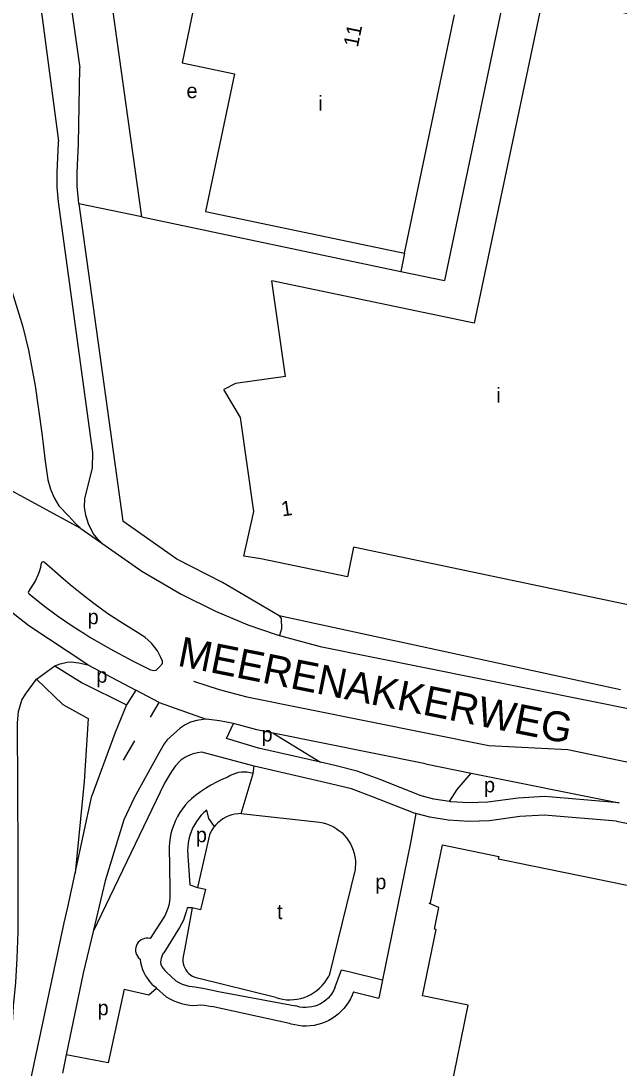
# Model space of a CAD drawing. Extents: x 157699 to 159683, y 381451 to 383293.
# Drawn here: x 157866.4 to 158027.2, y 382131.3 to 382412.9 of the extents above; entities that cross this region are included whole.
import ezdxf

# ---------------------------------------------------------------- set-up
doc = ezdxf.new("R2010")
doc.units = 0
for name, color, linetype in [('BLT_Basislijn', 7, 'Continuous'), ('BLT_Bebouwing', 7, 'Continuous'), ('BLT_Centroide', 7, 'Continuous'), ('BLT_Huisnummer', 7, 'Continuous'), ('BLT_Straatnaam_hoofdweg', 7, 'Continuous'), ('BLT_Vlakafsluiter', 7, 'Continuous')]:
    doc.layers.add(name, color=color, linetype=linetype)

msp = doc.modelspace()

# ---------------------------------------------------------------- linework, layer by layer
at = {"layer": 'BLT_Basislijn'}
for p, q in [((157872.09, 382472.97), (157882.28, 382400.27)), ((157866.68, 382454.83), (157876.58, 382380.56)), ((158001.58, 382444.81), (157980.31, 382343.07)), ((157898.92, 382360.23), (157882.04, 382363.73)), ((157882.04, 382363.73), (157893.81, 382278.36)), ((157898.92, 382360.23), (157968.55, 382345.54)), ((157969.59, 382350.49), (157968.55, 382345.54)), ((157968.55, 382345.54), (157980.31, 382343.07)), ((157884.42, 382239.74), (157897.33, 382232.92)), ((157870.66, 382235.92), (157875.53, 382239.49)), ((157901.27, 382225.73), (157903.61, 382229.63)), ((157934.26, 382221.36), (157946.93, 382213.56)), ((157893.97, 382214.09), (157897.06, 382219.34)), ((157929.17, 382212.52), (157915.11, 382216.32)), ((157928.85, 382210.55), (157929.17, 382212.52)), ((157925.66, 382199.77), (157946.74, 382197.44)), ((157972.62, 382199.75), (157972.44, 382198.77)), ((158026.58, 382197.69), (158050, 382192.97)), ((157917.11, 382194.04), (157913.9, 382179.85)), ((157906.37, 382187.82), (157906.46, 382177.08)), ((157956.26, 382184.71), (157949.27, 382156.23)), ((157912.45, 382174.4), (157910.51, 382163.61)), ((157912.45, 382174.4), (157911.14, 382174.45)), ((157904.77, 382171.72), (157901.15, 382166.19)), ((157909.05, 382169.12), (157904.87, 382162.35)), ((157910.51, 382163.61), (157910.05, 382161.33)), ((157905.54, 382157.15), (157908.12, 382154.77)), ((157934.99, 382150.3), (157913.9, 382155.55)), ((157954.62, 382157.33), (157963.66, 382155.07)), ((157894.23, 382152.57), (157889.92, 382132.71)), ((157902.9, 382152.8), (157902.26, 382153.36)), ((157905.51, 382150.5), (157902.9, 382152.8)), ((157963.66, 382155.07), (157962.66, 382150.17)), ((157919.53, 382151.89), (157940.23, 382148.05)), ((157955.81, 382151.88), (157962.66, 382150.17)), ((157938.66, 382143.3), (157917.74, 382147.86)), ((157878.62, 382134.87), (157877.6, 382129.97)), ((157889.92, 382132.71), (157878.62, 382134.87))]:
    msp.add_line(p, q, dxfattribs=at)
for points in [[(157898.92, 382360.23), (157888.73, 382433.33), (157887.31, 382443.49)], [(157842.49, 382416.11), (157844.46, 382406.06), (157846.72, 382396.15), (157849.16, 382386.42), (157851.39, 382378.58), (157854.48, 382368.73), (157861.08, 382349.18), (157864.09, 382339.92), (157866.95, 382330.66), (157868.51, 382324.33), (157870.3, 382314.78), (157872.07, 382302.05), (157872.93, 382294.52), (157873.7, 382289.49), (157874.36, 382286.95), (157875.34, 382284.62), (157876.6, 382282.47), (157879.28, 382279.71), (157880.94, 382277.93), (157882.56, 382276.42)], [(157882.04, 382363.73), (157881.89, 382364.83), (157881.58, 382368.49), (157881.55, 382372.14), (157881.93, 382379.89), (157882.28, 382400.27)], [(157888.17, 382272.5), (157887.12, 382273.51), (157885.9, 382275.07), (157884.61, 382277.7), (157883.9, 382280.03), (157883.5, 382282.17), (157883.65, 382284.48), (157885.71, 382292.61), (157885.81, 382296.89), (157876.56, 382364.24), (157876.22, 382368.24), (157876.19, 382372.25), (157876.58, 382380.06), (157876.58, 382380.56)], [(157882.56, 382276.42), (157888.17, 382272.5)], [(157920.63, 382261.91), (157908.34, 382268.17), (157893.81, 382278.36)], [(157888.17, 382272.5), (157898.92, 382264.98), (157909.49, 382258.73), (157918.7, 382254.18), (157927.48, 382250.55), (157935.02, 382247.89), (157935.97, 382247.63)], [(157872.79, 382267.31), (157872.47, 382267.48), (157872.09, 382267.35), (157871.79, 382266.77), (157871.68, 382265.89), (157871.38, 382264.79), (157870.99, 382263.85), (157870.4, 382262.43), (157869.77, 382261.47), (157868.46, 382259.48), (157868.42, 382259.28), (157868.5, 382259.05)], [(157868.5, 382259.05), (157868.65, 382258.88), (157872.4, 382255.83), (157876.26, 382252.98), (157880.21, 382250.28), (157883.6, 382248.07), (157884.95, 382247.23), (157890.44, 382244.03), (157896.43, 382240.83), (157901.28, 382238.43), (157902.2, 382238.23), (157902.77, 382238.34), (157903.15, 382238.64), (157903.71, 382239.23), (157904.46, 382240.09), (157904.54, 382240.44), (157904.47, 382240.79), (157904.07, 382241.76), (157903.11, 382243.55), (157901.58, 382245.56), (157899.71, 382247.2), (157897.31, 382248.75), (157893.98, 382250.78), (157889.81, 382253.49), (157886.04, 382256.24), (157883.24, 382258.36), (157879.66, 382261.29), (157877.77, 382262.89), (157874.88, 382265.45), (157872.79, 382267.31)], [(157935.82, 382252.96), (157920.63, 382261.91)], [(158027.64, 382233.05), (157935.82, 382252.96)], [(157935.82, 382252.96), (157936.38, 382252.21), (157936.45, 382249.43), (157935.97, 382247.63)], [(157935.97, 382247.63), (157946.89, 382244.69), (158075.13, 382218.86), (158097.02, 382209.33), (158189.06, 382190.81)], [(157875.53, 382239.49), (157876.97, 382240.03), (157878.88, 382240.5), (157879.93, 382240.61), (157881.97, 382240.29), (157884.42, 382239.74)], [(157875.53, 382239.49), (157882.94, 382234.92), (157894.8, 382229.01)], [(157870.06, 381934.31), (157867.05, 381973.8), (157865.68, 381993.87), (157864.55, 382022.12), (157863.4, 382041.04), (157863.08, 382054.8), (157862.87, 382062.83), (157862.77, 382082.25), (157862.74, 382092.84), (157862.8, 382114.69), (157863.2, 382126.22), (157863.95, 382140.63), (157864.47, 382147.95), (157865.05, 382154.36), (157865.43, 382160.91), (157865.68, 382167.86), (157865.71, 382188.66), (157865.51, 382224.16), (157865.78, 382227.21), (157866.65, 382230.22), (157867.7, 382231.89), (157870.66, 382235.92)], [(157870.66, 382235.92), (157877.71, 382229.09), (157884.48, 382225.3), (157883.43, 382208.35), (157881, 382183.71)], [(157912.82, 382235.37), (157919.74, 382233.13), (157927.13, 382231.2), (157992.2, 382218.03), (158013.48, 382217.01), (158148.74, 382188.63), (158163.94, 382185.79)], [(157897.33, 382232.92), (157894.8, 382229.01)], [(157894.8, 382229.01), (157891.8, 382221.56), (157885.54, 382204.57)], [(157916.22, 382225.12), (157915.45, 382225.03), (157913.73, 382224.81), (157912.06, 382224.32), (157910.59, 382223.63), (157909.22, 382222.75), (157905.76, 382219.55)], [(157923.54, 382223.98), (157919.79, 382224.7), (157916.22, 382225.12)], [(157946.93, 382213.56), (157930.29, 382217.39), (157921.69, 382219.92), (157923.54, 382223.98)], [(157934.26, 382221.36), (157929.87, 382222.24), (157923.9, 382223.91), (157923.54, 382223.98)], [(157975.17, 382213.15), (157934.26, 382221.36)], [(157905.76, 382219.55), (157904.97, 382218.5), (157903.5, 382215.98), (157896.88, 382204.03), (157894.07, 382198.04), (157889.06, 382181.71), (157885.84, 382168.02)], [(157915.11, 382216.32), (157913.93, 382216.14), (157912.73, 382215.85), (157911.58, 382215.42), (157910.49, 382214.86), (157909.46, 382214.17), (157909.23, 382213.92), (157908.03, 382212.58), (157906.9, 382211.1), (157905.01, 382207.97), (157885.84, 382168.02)], [(157972.62, 382199.75), (157972.45, 382199.79), (157960.95, 382204.31), (157955.33, 382206.39), (157949.69, 382207.79), (157929.17, 382212.52)], [(157981.67, 382202.97), (157977.43, 382203.67), (157974, 382204.55), (157962.73, 382208.99), (157956.8, 382211.18), (157950.85, 382212.65), (157946.93, 382213.56)], [(157975.17, 382213.15), (157987.46, 382210.67)], [(157922.02, 382209.55), (157920.48, 382208.9), (157918.97, 382208.18), (157917.51, 382207.39), (157916.08, 382206.52), (157914.69, 382205.59), (157913.35, 382204.59), (157912.32, 382203.75)], [(157928.85, 382210.55), (157928.08, 382210.75), (157927.3, 382210.88), (157926.51, 382210.92), (157925.71, 382210.89), (157924.93, 382210.77), (157924.16, 382210.58), (157923.41, 382210.31), (157922.7, 382209.97), (157922.02, 382209.55)], [(157925.66, 382199.77), (157928.85, 382210.55)], [(157981.67, 382202.97), (157983.7, 382206.21), (157987.46, 382210.67)], [(157987.46, 382210.67), (158027.23, 382202.65)], [(157881, 382183.71), (157885.54, 382204.57)], [(157912.32, 382203.75), (157911.44, 382202.9), (157910.62, 382201.99), (157909.87, 382201.03), (157909.18, 382200.03), (157908.56, 382198.98), (157908, 382197.89), (157907.52, 382196.76), (157907.11, 382195.61), (157906.78, 382194.43), (157906.53, 382193.24), (157906.36, 382192.03), (157906.26, 382190.81), (157906.25, 382189.59), (157906.31, 382188.37), (157906.37, 382187.82)], [(158027.23, 382202.65), (158007.2, 382204.36), (158000.07, 382203.92), (157991.93, 382202.82), (157986.91, 382202.63), (157981.89, 382202.93), (157981.67, 382202.97)], [(157916.45, 382200.71), (157915.65, 382200.03), (157914.91, 382199.3), (157914.23, 382198.51), (157913.61, 382197.66), (157913.06, 382196.78), (157912.57, 382195.85), (157912.16, 382194.89), (157911.82, 382193.9), (157911.56, 382192.89), (157911.38, 382191.86), (157911.27, 382190.82), (157911.25, 382189.78), (157911.3, 382188.74), (157911.34, 382188.4)], [(157918.44, 382196.27), (157916.95, 382198.4), (157916.45, 382200.71)], [(157925.66, 382199.77), (157924.8, 382199.73), (157923.95, 382199.6), (157923.11, 382199.4), (157922.29, 382199.12), (157921.5, 382198.77), (157920.75, 382198.35), (157920.05, 382197.85), (157919.39, 382197.3), (157918.78, 382196.68), (157918.44, 382196.27)], [(157946.74, 382197.44), (157947.67, 382197.26), (157948.59, 382197), (157949.48, 382196.67), (157950.34, 382196.27), (157951.16, 382195.79), (157951.94, 382195.24), (157952.67, 382194.64), (157953.34, 382193.97), (157953.96, 382193.25), (157954.52, 382192.48), (157955, 382191.66), (157955.42, 382190.81), (157955.77, 382189.93), (157956.04, 382189.02), (157956.23, 382188.09), (157956.34, 382187.14), (157956.37, 382186.19), (157956.32, 382185.24), (157956.26, 382184.71)], [(157972.44, 382198.77), (157971.17, 382191.89), (157963.66, 382155.07)], [(158026.58, 382197.69), (158007.14, 382199.34), (158000.56, 382198.94), (157992.36, 382197.83), (157986.85, 382197.62), (157981.33, 382197.95), (157976.4, 382198.77), (157972.62, 382199.75)], [(157918.44, 382196.27), (157918.24, 382196.02), (157917.75, 382195.3), (157917.34, 382194.54), (157917.11, 382194.04)], [(157911.34, 382188.4), (157911.87, 382180.62), (157913.9, 382179.85)], [(157879.03, 382174.64), (157881, 382183.71)], [(157913.9, 382179.85), (157916.04, 382179.46), (157914.68, 382173.92), (157912.45, 382174.4)], [(157906.46, 382177.08), (157906.36, 382176.12), (157906.18, 382175.17), (157905.92, 382174.24), (157905.59, 382173.33), (157905.18, 382172.45), (157904.77, 382171.72)], [(157865.93, 382092.23), (157865.77, 382105.36), (157867.28, 382119.86), (157878.1, 382170.39), (157879.03, 382174.64)], [(157911.14, 382174.45), (157910.87, 382173.33), (157910.52, 382172.23), (157910.1, 382171.15), (157909.6, 382170.11), (157909.05, 382169.12)], [(157885.84, 382168.02), (157883.21, 382156.84), (157878.62, 382134.87)], [(157901.15, 382166.19), (157900.65, 382166.27), (157900.15, 382166.27), (157899.65, 382166.19), (157899.18, 382166.03), (157898.73, 382165.8), (157898.33, 382165.5), (157897.98, 382165.15), (157897.69, 382164.74), (157897.47, 382164.29), (157897.32, 382163.8), (157897.25, 382163.31), (157897.27, 382162.81), (157897.36, 382162.31), (157897.52, 382161.84), (157897.77, 382161.4), (157898.07, 382161), (157898.48, 382160.63)], [(157904.28, 382158.65), (157904.14, 382159.21), (157904.08, 382159.77), (157904.1, 382160.35), (157904.2, 382160.91), (157904.37, 382161.45), (157904.62, 382161.97), (157904.87, 382162.35)], [(157910.05, 382161.33), (157909.98, 382160.71), (157909.98, 382160.07), (157910.06, 382159.45), (157910.22, 382158.84), (157910.46, 382158.26), (157910.77, 382157.71), (157911.14, 382157.2), (157911.58, 382156.75), (157912.07, 382156.35), (157912.6, 382156.02), (157913.18, 382155.76), (157913.78, 382155.58), (157913.9, 382155.55)], [(157898.48, 382160.63), (157898.62, 382159.7), (157898.83, 382158.78), (157899.12, 382157.88), (157899.49, 382157.01), (157899.93, 382156.18), (157900.44, 382155.39), (157901.01, 382154.64), (157901.65, 382153.94), (157902.26, 382153.36)], [(157904.28, 382158.65), (157904.67, 382158.07), (157905.12, 382157.54), (157905.54, 382157.15)], [(157934.99, 382150.3), (157935.92, 382150.03), (157936.87, 382149.84), (157937.83, 382149.72), (157938.8, 382149.69), (157939.77, 382149.74), (157940.73, 382149.86), (157941.68, 382150.07), (157942.61, 382150.35), (157943.51, 382150.71), (157944.38, 382151.14), (157945.21, 382151.64), (157946, 382152.2), (157946.73, 382152.83), (157947.42, 382153.52), (157948.04, 382154.27), (157948.6, 382155.06), (157949.1, 382155.89), (157949.27, 382156.23)], [(157950.84, 382152.87), (157952.66, 382157.72), (157954.62, 382157.33)], [(157894.23, 382152.57), (157900.83, 382151.02), (157902.9, 382152.8)], [(157908.12, 382154.77), (157908.93, 382154.31), (157909.79, 382153.93), (157910.67, 382153.62), (157911.58, 382153.4), (157912.5, 382153.24), (157913.18, 382153.18)], [(157913.18, 382153.18), (157915.36, 382152.82), (157917.52, 382152.38), (157919.53, 382151.89)], [(157950.84, 382152.87), (157950.48, 382152.12), (157950.05, 382151.41), (157949.56, 382150.74), (157949, 382150.13), (157948.38, 382149.57), (157947.72, 382149.08), (157947.01, 382148.65), (157946.26, 382148.29), (157945.48, 382148.01), (157944.68, 382147.8), (157943.86, 382147.67), (157943.03, 382147.62), (157942.2, 382147.65), (157941.38, 382147.75), (157940.57, 382147.94), (157940.23, 382148.05)], [(157905.51, 382150.5), (157906.49, 382149.94), (157907.51, 382149.46), (157908.57, 382149.05), (157909.64, 382148.72), (157910.74, 382148.46), (157911.86, 382148.29), (157912.89, 382148.19)], [(157955.81, 382151.88), (157955.44, 382150.91), (157955, 382149.96), (157954.48, 382149.05), (157953.9, 382148.19), (157953.25, 382147.37), (157952.54, 382146.61), (157951.78, 382145.9), (157950.96, 382145.25), (157950.1, 382144.66), (157949.19, 382144.15), (157948.25, 382143.7), (157947.27, 382143.33), (157946.27, 382143.04), (157945.25, 382142.82), (157944.22, 382142.68), (157943.18, 382142.62), (157942.14, 382142.64), (157941.1, 382142.74), (157940.07, 382142.92), (157939.06, 382143.17), (157938.66, 382143.3)], [(157912.89, 382148.19), (157913.86, 382148.29), (157914.84, 382148.3), (157915.82, 382148.24), (157916.79, 382148.09), (157917.74, 382147.86)]]:
    msp.add_lwpolyline(points, dxfattribs=at)
at = {"layer": 'BLT_Bebouwing'}
for p, q in [((157969.59, 382350.49), (157982.96, 382414.52)), ((157937.55, 382317.33), (157933.9, 382343.05)), ((157973.28, 382082.59), (157986.71, 382148.21))]:
    msp.add_line(p, q, dxfattribs=at)
for points in [[(157916.28, 382432.84), (157909.75, 382401.65), (157923.82, 382398.69)], [(158064.19, 382407.61), (158006.84, 382419.65), (157988.31, 382331.62), (157933.9, 382343.05)], [(157923.82, 382398.69), (157916.09, 382361.66), (157969.59, 382350.49)], [(157937.55, 382317.33), (157924.12, 382315.45), (157921.02, 382313.81)], [(157926.4, 382268.95), (157929.06, 382280.97), (157925.47, 382306.23), (157921.02, 382313.81)], [(157955.86, 382271.39), (157954.19, 382263.38), (157930.89, 382268.25), (157926.4, 382268.95)], [(158032.2, 382255.36), (157955.86, 382271.39)], [(157986.71, 382148.21), (157974.36, 382150.73), (157978.02, 382168.57), (157977.64, 382168.65), (157978.82, 382174.54), (157976.26, 382175.56), (157976.36, 382175.86), (157976.52, 382175.8), (157979.75, 382191.37), (157994.92, 382188.24), (157994.77, 382187.6), (157997.38, 382187.07)], [(157997.38, 382187.07), (158000, 382186.53), (158050, 382176.3)]]:
    msp.add_lwpolyline(points, dxfattribs=at)
at = {"layer": 'BLT_Vlakafsluiter'}
for p, q in [((157882.56, 382276.42), (157859.77, 382288.75)), ((157884.42, 382239.74), (157868.58, 382250.23)), ((157903.61, 382229.63), (157897.33, 382232.92)), ((157903.61, 382229.63), (157916.22, 382225.12))]:
    msp.add_line(p, q, dxfattribs=at)
msp.add_lwpolyline([(157868.58, 382250.23), (157864.81, 382253.21), (157853.53, 382262.43)], dxfattribs=at)

# ---------------------------------------------------------------- texts
at = {"layer": 'BLT_Centroide'}
for s, p in [('e', (157910.94, 382392.13)), ('i', (157946.36, 382388.77)), ('i', (157994.25, 382310.28)), ('p', (157884.37, 382250.68)), ('p', (157886.7, 382234.94)), ('p', (157931.11, 382219.14)), ('p', (157990.92, 382205.47)), ('p', (157913.46, 382192.06)), ('p', (157961.7, 382179.43)), ('t', (157935.29, 382171.39)), ('p', (157887.05, 382145.54))]:
    msp.add_text(s, height=4, dxfattribs=at).set_placement(p)
at = {"layer": 'BLT_Huisnummer'}
for s, rotation, p in [('11', 78.3796, (157957, 382405.65)), ('1', 8.1085, (157936.68, 382279.65))]:
    msp.add_text(s, height=4, rotation=rotation, dxfattribs=at).set_placement(p)
at = {"layer": 'BLT_Straatnaam_hoofdweg'}
msp.add_text('MEERENAKKERWEG', height=8, rotation=348.7122, dxfattribs=at).set_placement((157908.26, 382239.57))

doc.saveas('drawing.dxf')
